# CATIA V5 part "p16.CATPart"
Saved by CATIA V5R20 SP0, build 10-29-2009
Part number: p16
Bounding box of the stored display mesh (mm): x -20 to -5, y 26.602 to 58.072, z 90.836 to 122.949
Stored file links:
  D:\Dropbox\IAO_2011\MMS_GR2\IAO_2011_1439_jlicbarski\p16.CATPart
  D:\Dropbox\IAO_2011\MMS_GR2\IAO_2011_1439_jlicbarski\train.CATProduct
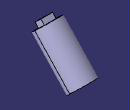
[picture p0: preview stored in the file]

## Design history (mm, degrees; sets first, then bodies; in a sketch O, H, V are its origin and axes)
AxisSystem1: origin (0, 0, 0), X (1, 0, 0), Y (0, 1, 0), Z (0, 0, 1)
Set1
  Plane1: linked copy from another document
  Line1: linked copy from another document
  Plane2: linked copy from another document
  Plane3: linked copy from another document
  Line2: linked copy from another document
Body1 (main body)
  Sketch1 on Plane2, origin (0, -45.7982, 48.6606), H (1, 0, 0), V (0, 0.7282, 0.6854)
    line L1 (-15.931, 106.3164) -> (-9.0687, 106.3164)
    line L2 (-9.0687, 106.3164) -> (-9.0687, 101.6187)
    line L3 (-9.0687, 101.6187) -> (-15.931, 101.6187)
    line L4 (-15.931, 101.6187) -> (-15.931, 106.3164)
    reference intersected line E1 through (-12.5, 0) direction (0, 1) from Plane3
    reference intersected line E2 through (-12.5, 0) direction (0, 1) from Plane3
    distance L2 E1 = 3.4313
    distance L4 E2 = 3.431
  Pad1: profile Sketch1, direction (0, 0.6854, -0.7282), length 3
  Sketch2 on end face of Pad1, origin (0, -43.7421, 46.476), H (-1, 0, 0), V (0, 0.7282, 0.6854)
    circle A1 centre (12.5, 104.0898) radius 7.5
    reference projected point E1 (12.5, 104.0898) from Line2
    radius A1 = 7.5
    distance A1 E1 = 7.5
  Pad2: profile Sketch2, direction (0, 0.6854, -0.7282), length 30
  Sketch3 on end face of Pad2, origin (0, -23.1811, 24.63), H (-1, 0, 0), V (0, 0.7282, 0.6854)
    circle A1 centre (12.5, 104.0898) radius 1.75
    reference projected point E1 (12.5, 104.0898) from Line2
    radius A1 = 1.75
    distance A1 E1 = 1.75
  Pocket1: profile Sketch3, direction (0, -0.6854, 0.7282), length 2
  Sketch4 on end face of Pocket1, origin (0, -24.5519, 26.0864), H (-1, 0, 0), V (0, 0.7282, 0.6854)
    circle A1 centre (12.5, 104.0898) radius 5.5
    reference projected point E1 (12.5, 104.0898) from Line2
    radius A1 = 5.5
    distance A1 E1 = 5.5
  Pocket2: profile Sketch4, direction (0, -0.6854, 0.7282), length 26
